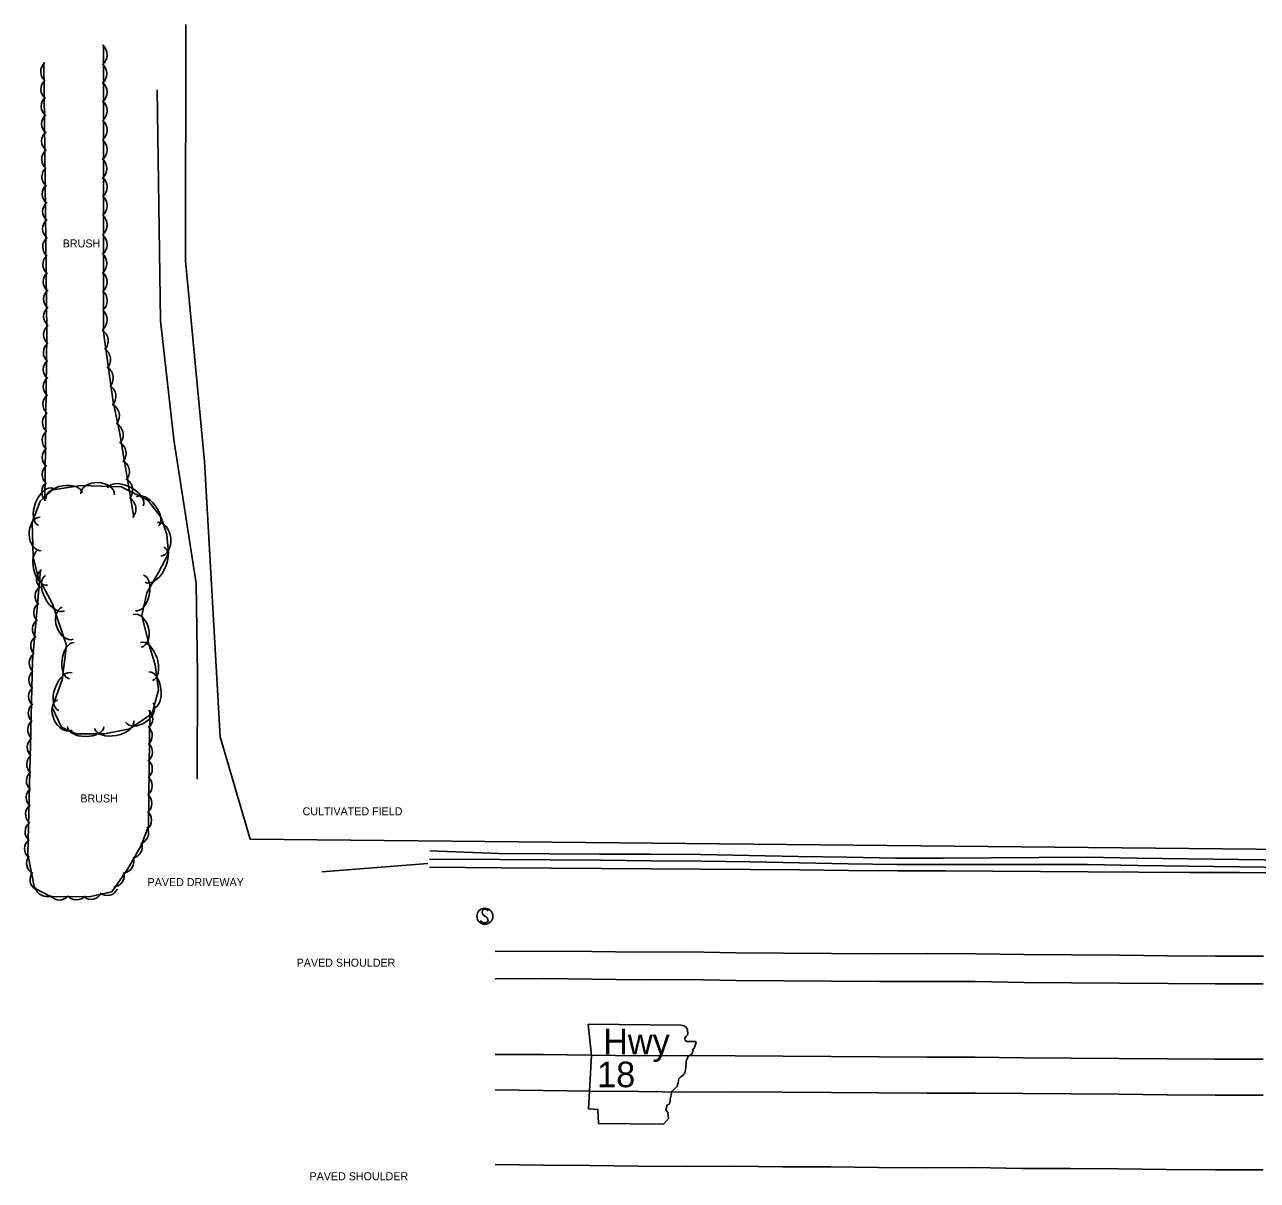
# Model space of a CAD drawing. Extents: x 1802180 to 1804859, y 572524 to 575172.
# Drawn here: x 1802201.2 to 1802586.4, y 573786 to 574147.1 of the extents above; entities that cross this region are included whole.
import ezdxf

# ---------------------------------------------------------------- set-up
doc = ezdxf.new("R2010")
doc.units = 0
for name, color, linetype in [('EX_EDGE_PAVEMENT', 7, 'Continuous'), ('EX_SHOULDER', 7, 'Continuous'), ('S_DITCHLINE', 7, 'Continuous'), ('S_DRIVEWAY_ANNOT', 7, 'Continuous'), ('S_HWY_SYMBOLS', 7, 'Continuous'), ('S_MISC_BOUNDARY', 7, 'Continuous'), ('S_MISC_BOUNDARY_ANNOT', 7, 'Continuous'), ('S_PAVEMENT_CROWN', 7, 'Continuous'), ('S_SHOULDER_ANNOT', 7, 'Continuous'), ('S_SIGN', 7, 'Continuous'), ('S_STREAM', 7, 'Continuous'), ('S_TRAILS', 7, 'Continuous'), ('S_TREE', 7, 'Continuous'), ('S_TREE_ANNOT', 7, 'Continuous')]:
    doc.layers.add(name, color=color, linetype=linetype)

msp = doc.modelspace()

# ---------------------------------------------------------------- linework, layer by layer
at = {"layer": 'EX_EDGE_PAVEMENT'}
for points in [[(1802588.23, 573847.4), (1802573.23, 573847.42), (1802558.48, 573847.5), (1802543.36, 573847.68), (1802528.36, 573847.78), (1802513.47, 573847.87), (1802498.25, 573848.16), (1802483.25, 573848.18), (1802468.33, 573848.18), (1802453.32, 573848.24), (1802438.39, 573848.34), (1802423.46, 573848.49), (1802408.33, 573848.75), (1802393.53, 573848.7), (1802378.53, 573848.9), (1802363.22, 573849.13), (1802348.22, 573849.03)], [(1802588.17, 573789.3), (1802573.17, 573789.32), (1802557.81, 573789.42), (1802542.98, 573789.59), (1802527.98, 573789.69), (1802512.83, 573789.79), (1802498.15, 573790.07), (1802483.15, 573789.99), (1802468.03, 573790.1), (1802453.04, 573790.23), (1802437.95, 573790.31), (1802422.84, 573790.47), (1802408.03, 573790.35), (1802392.76, 573790.46), (1802377.75, 573790.63), (1802363.2, 573790.82), (1802348.2, 573790.98)]]:
    msp.add_lwpolyline(points, dxfattribs=at)
at = {"layer": 'EX_SHOULDER'}
msp.add_lwpolyline([(1802348.18, 573857.56), (1802363.18, 573857.66), (1802378.37, 573857.51), (1802393.35, 573857.31), (1802408.39, 573857.4), (1802423.39, 573857.14), (1802438.32, 573856.99), (1802453.29, 573856.92), (1802468.27, 573856.86), (1802483.23, 573856.87), (1802498.39, 573856.84), (1802513.39, 573856.56), (1802528.29, 573856.46), (1802543.28, 573856.36), (1802558.33, 573856.19), (1802573.28, 573856.1), (1802588.27, 573856.09)], dxfattribs=at)
at = {"layer": 'S_DITCHLINE'}
for points in [[(1802596.5, 573883.74), (1802580.71, 573883.97), (1802564.91, 573884.21), (1802549.11, 573884.44), (1802533.32, 573884.68), (1802518.43, 573884.68), (1802503.55, 573884.68), (1802488.66, 573884.68), (1802473.77, 573884.69), (1802458.52, 573884.96), (1802443.27, 573885.24), (1802428.02, 573885.51), (1802412.77, 573885.79), (1802397.01, 573885.91), (1802381.24, 573886.04), (1802365.47, 573886.17), (1802349.7, 573886.29), (1802327.68, 573886.43)], [(1802596.44, 573886.07), (1802580.57, 573886.3), (1802564.71, 573886.53), (1802548.85, 573886.75), (1802532.99, 573886.98), (1802518.08, 573886.91), (1802503.17, 573886.83), (1802488.26, 573886.75), (1802473.35, 573886.68), (1802458.1, 573886.97), (1802442.86, 573887.26), (1802427.61, 573887.55), (1802412.37, 573887.84), (1802396.61, 573887.91), (1802380.85, 573887.98), (1802365.08, 573888.05), (1802349.32, 573888.12), (1802327.76, 573888.98)], [(1802596.64, 573882.1), (1802580.85, 573882.19), (1802565.05, 573882.27), (1802549.26, 573882.36), (1802533.47, 573882.45), (1802518.61, 573882.53), (1802503.75, 573882.62), (1802488.89, 573882.7), (1802474.03, 573882.78), (1802458.67, 573882.9), (1802443.32, 573883.01), (1802427.96, 573883.13), (1802412.61, 573883.24), (1802397, 573883.36), (1802381.4, 573883.48), (1802365.79, 573883.59), (1802350.19, 573883.71), (1802327.66, 573883.88)]]:
    msp.add_lwpolyline(points, dxfattribs=at)
at = {"layer": 'S_HWY_SYMBOLS'}
msp.add_lwpolyline([(1802377.27, 573834.79), (1802378.27, 573825), (1802377.42, 573808.38), (1802380.3, 573808.21), (1802380.47, 573803.81), (1802400.82, 573803.64), (1802402.34, 573805.33), (1802402.17, 573807.2), (1802401.5, 573808.05), (1802402, 573809.57), (1802402.68, 573809.91), (1802402.85, 573810.76), (1802402.85, 573811.44), (1802403.19, 573812.62), (1802403.36, 573813.81), (1802405.06, 573815.34), (1802405.23, 573815.85), (1802405.4, 573816.52), (1802405.57, 573817.71), (1802406.24, 573818.39), (1802406.92, 573818.9), (1802407.43, 573819.58), (1802407.6, 573820.25), (1802407.77, 573821.1), (1802407.77, 573821.78), (1802407.94, 573822.46), (1802407.94, 573823.48), (1802408.11, 573823.65), (1802408.45, 573824.49), (1802408.62, 573824.83), (1802409.63, 573825.51), (1802409.97, 573826.36), (1802409.97, 573826.87), (1802410.48, 573827.55), (1802410.99, 573829.07), (1802410.82, 573829.41), (1802408.11, 573829.41), (1802407.6, 573829.75), (1802407.43, 573830.6), (1802407.94, 573831.11), (1802408.45, 573831.61), (1802408.28, 573833.14), (1802407.77, 573833.99), (1802407.26, 573834.33), (1802406.24, 573834.5), (1802377.27, 573834.79)], dxfattribs=at)
at = {"layer": 'S_MISC_BOUNDARY'}
msp.add_lwpolyline([(1802879.39, 573886.61), (1802271.63, 573892.66), (1802262.29, 573924.58), (1802257.37, 574010.6), (1802251.41, 574073.29), (1802251.52, 574147.13)], dxfattribs=at)
at = {"layer": 'S_PAVEMENT_CROWN'}
for points in [[(1802588.21, 573823.87), (1802573.21, 573823.89), (1802558.21, 573823.98), (1802543.21, 573824.15), (1802528.21, 573824.25), (1802513.21, 573824.35), (1802498.21, 573824.52), (1802483.21, 573824.54), (1802468.21, 573824.62), (1802453.21, 573824.69), (1802438.21, 573824.81), (1802423.21, 573824.97), (1802408.21, 573825.04), (1802393.21, 573824.92), (1802378.21, 573825.12), (1802363.21, 573825.32), (1802348.21, 573825.33)], [(1802348.21, 573814.3), (1802363.21, 573814.13), (1802378.06, 573813.94), (1802393.06, 573813.78), (1802408.15, 573813.61), (1802423.09, 573813.72), (1802438.13, 573813.56), (1802453.16, 573813.44), (1802468.15, 573813.37), (1802483.19, 573813.25), (1802498.19, 573813.31), (1802513.08, 573813.13), (1802528.13, 573813.03), (1802543.13, 573812.94), (1802558.08, 573812.76), (1802573.19, 573812.67), (1802588.19, 573812.65)]]:
    msp.add_lwpolyline(points, dxfattribs=at)
at = {"layer": 'S_SIGN'}
msp.add_circle((1802344.99, 573868.56), 2.5, dxfattribs=at)
for centre, radius, start, end in [((1802344.83, 573867.74), 1.28, 204.641, 335.359), ((1802345.68, 573869.89), 1.51, 167.1196, 241.9813), ((1802345.06, 573869.83), 0.952, 16.5258, 156.8957), ((1802344.58, 573867.22), 1.4, 358.6529, 73.7063)]:
    msp.add_arc(centre, radius, start, end, dxfattribs=at)
at = {"layer": 'S_STREAM'}
msp.add_lwpolyline([(1802294.01, 573882.47), (1802327.14, 573885.03)], dxfattribs=at)
at = {"layer": 'S_TRAILS'}
msp.add_lwpolyline([(1802242.56, 574126.8), (1802243.66, 574054.55), (1802247.82, 574017.54), (1802254.8, 573972.48), (1802255.19, 573944.13), (1802255.12, 573911.35)], dxfattribs=at)
at = {"layer": 'S_TREE'}
for points in [[(1802225.86, 574140.8), (1802225.87, 574051.01), (1802228.83, 574029.25), (1802230.77, 574019.96), (1802235.29, 573993.25)], [(1802207.46, 573998.36), (1802208.15, 574050.85), (1802207.19, 574135.29)], [(1802218.8, 574003.12), (1802231.39, 574002.73), (1802239.69, 573998.56), (1802243.81, 573993.12), (1802245.63, 573987.8), (1802246.18, 573981.85), (1802243, 573975.93), (1802239.41, 573969.59), (1802237.8, 573962.54), (1802240.07, 573953.22), (1802241.97, 573947.09), (1802243.01, 573939.25), (1802240.99, 573931.92), (1802234.08, 573927.1), (1802226.11, 573925.52), (1802217.25, 573925.56), (1802212.69, 573927.67), (1802209.78, 573933.73), (1802212.86, 573942.42), (1802214.29, 573953.2), (1802209.88, 573966.14), (1802205.39, 573974.55), (1802203.89, 573980.89), (1802203.5, 573991.71), (1802206.06, 573998.24), (1802210.02, 574001.74), (1802218.8, 574003.12)], [(1802240.26, 573932.95), (1802239.92, 573896.69), (1802237.61, 573890.68), (1802233.42, 573883.37), (1802228.41, 573876.18), (1802221.77, 573874.68), (1802209.42, 573874.61), (1802204.23, 573877.33), (1802202.14, 573887.97), (1802203.62, 573948.41), (1802206.15, 573976.82)]]:
    msp.add_lwpolyline(points, dxfattribs=at)
for centre, radius, start, end in [((1802222.94, 574137.7), 4, 309.2056, 50.8025), ((1802209.89, 574132.46), 3.69, 129.8556, 231.4525), ((1802222.86, 574131.84), 4, 309.2056, 50.8025), ((1802209.95, 574126.94), 3.69, 129.8556, 231.4525), ((1802222.94, 574126.04), 4, 309.2056, 50.8025), ((1802210.04, 574121.57), 3.69, 129.8556, 231.4525), ((1802222.98, 574120.21), 4, 309.2056, 50.8025), ((1802210.18, 574116.21), 3.69, 129.8556, 231.4525), ((1802210.17, 574110.8), 3.69, 129.8556, 231.4525), ((1802222.98, 574114.24), 4, 309.2056, 50.8025), ((1802222.94, 574108.04), 4, 309.2056, 50.8025), ((1802210.2, 574105.07), 3.69, 129.8556, 231.4525), ((1802210.26, 574099.56), 3.69, 129.8556, 231.4525), ((1802222.86, 574102.18), 4, 309.2056, 50.8025), ((1802222.94, 574096.37), 4, 309.2056, 50.8025), ((1802210.36, 574094.18), 3.69, 129.8556, 231.4525), ((1802210.49, 574088.82), 3.69, 129.8556, 231.4525), ((1802222.98, 574090.55), 4, 309.2056, 50.8025), ((1802222.98, 574084.57), 4, 309.2056, 50.8025), ((1802210.48, 574083.41), 3.69, 129.8556, 231.4525), ((1802210.51, 574077.69), 3.69, 129.8556, 231.4525), ((1802222.94, 574078.37), 4, 309.2056, 50.8025), ((1802222.86, 574072.51), 4, 309.2056, 50.8025), ((1802210.57, 574072.17), 3.69, 129.8556, 231.4525), ((1802210.67, 574066.79), 3.69, 129.8556, 231.4525), ((1802222.95, 574066.71), 4, 309.2056, 50.8025), ((1802210.8, 574061.44), 3.69, 129.8556, 231.4525), ((1802222.99, 574060.88), 4, 309.2056, 50.8025), ((1802210.79, 574056.03), 3.69, 129.8556, 231.4525), ((1802222.98, 574054.91), 4, 309.2056, 50.8025), ((1802210.81, 574050.23), 3.69, 128.4476, 230.0445), ((1802223.29, 574048.33), 4, 316.9587, 58.5556), ((1802210.73, 574044.72), 3.69, 128.4476, 230.0445), ((1802224, 574042.51), 4, 316.9587, 58.5556), ((1802210.7, 574039.34), 3.69, 128.4476, 230.0445), ((1802210.7, 574033.98), 3.69, 128.4476, 230.0445), ((1802224.86, 574036.78), 4, 316.9587, 58.5556), ((1802225.68, 574031.01), 4, 316.9587, 58.5556), ((1802210.56, 574028.57), 3.69, 128.4476, 230.0445), ((1802210.45, 574022.85), 3.69, 128.4476, 230.0445), ((1802226.79, 574024.93), 4, 321.0046, 62.6015), ((1802227.98, 574018.96), 4, 318.7984, 60.3953), ((1802210.37, 574017.33), 3.69, 128.4476, 230.0445), ((1802210.34, 574011.95), 3.69, 128.4476, 230.0445), ((1802228.88, 574013.17), 4, 318.7984, 60.3953), ((1802229.92, 574007.46), 4, 318.7984, 60.3953), ((1802210.34, 574006.6), 3.69, 128.4476, 230.0445), ((1802210.2, 574001.19), 3.69, 128.4476, 230.0445), ((1802230.93, 574001.72), 4, 318.7984, 60.3953), ((1802231.93, 573995.83), 4, 318.7984, 60.3953), ((1802208.46, 573973.85), 3.56, 124.1179, 225.7148), ((1802207.99, 573968.55), 3.56, 124.1179, 225.7148), ((1802207.56, 573963.39), 3.56, 124.1179, 225.7148), ((1802207.17, 573958.24), 3.56, 124.1179, 225.7148), ((1802206.64, 573953.05), 3.56, 124.1179, 225.7148), ((1802206.17, 573947.72), 3.56, 127.7965, 229.3934), ((1802206.04, 573942.41), 3.56, 127.7965, 229.3934), ((1802205.95, 573937.23), 3.56, 127.7965, 229.3934), ((1802205.89, 573932.07), 3.56, 127.7965, 229.3934), ((1802237.63, 573930.21), 3.56, 308.6755, 50.2725), ((1802205.69, 573926.86), 3.56, 127.7965, 229.3934), ((1802237.51, 573925), 3.56, 308.6755, 50.2725), ((1802205.52, 573921.34), 3.56, 127.7965, 229.3934), ((1802237.54, 573919.84), 3.56, 308.6755, 50.2725), ((1802205.39, 573916.03), 3.56, 127.7965, 229.3934), ((1802237.52, 573914.65), 3.56, 308.6755, 50.2725), ((1802205.3, 573910.85), 3.56, 127.7965, 229.3934), ((1802237.47, 573909.34), 3.56, 308.6755, 50.2725), ((1802205.24, 573905.68), 3.56, 127.7965, 229.3934), ((1802237.39, 573903.82), 3.56, 308.6755, 50.2725), ((1802205.04, 573900.48), 3.56, 127.7965, 229.3934), ((1802237.27, 573898.61), 3.56, 308.6755, 50.2725), ((1802204.88, 573894.96), 3.56, 127.7965, 229.3934), ((1802236.33, 573894.58), 3.56, 288.1666, 29.7635), ((1802204.74, 573889.65), 3.56, 127.7965, 229.3934), ((1802234.39, 573890.21), 3.56, 279.3667, 20.9636), ((1802205.35, 573885.09), 3.56, 140.321, 241.9179), ((1802231.74, 573885.6), 3.56, 279.3667, 20.9636), ((1802206.42, 573880.04), 3.56, 140.321, 241.9179), ((1802228.76, 573881.23), 3.56, 274.3179, 15.9149), ((1802208.07, 573878.25), 3.56, 191.5099, 293.1068), ((1802212.03, 573877.19), 3.56, 219.5408, 321.1377), ((1802217.35, 573877.22), 3.56, 219.5408, 321.1377), ((1802221.96, 573877.39), 3.56, 231.9504, 333.5473), ((1802226.97, 573878.6), 3.56, 231.9504, 333.5473)]:
    msp.add_arc(centre, radius, start, end, dxfattribs=at)
for centre, major_axis, ratio in [((1802207.81, 573996.5), (-2.29, -5.82), 0.55008), ((1802213.52, 574000), (-5.63, -0.89), 0.540699), ((1802224, 574000.42), (-5.28, 0.17), 0.685311), ((1802232.65, 573999.56), (-5.59, 2.81), 0.55008), ((1802239.53, 573995.03), (-3.44, 4.54), 0.540699), ((1802206.18, 573987.98), (0.19, -5.28), 0.685311), ((1802243.22, 573986.33), (-0.48, 5.26), 0.685311), ((1802207.01, 573977.53), (1.31, -5.55), 0.540699), ((1802241.76, 573978.4), (2.96, 5.51), 0.55008), ((1802210.64, 573969.52), (2.95, -5.51), 0.55008), ((1802237.08, 573969.53), (1.27, 5.55), 0.540699), ((1802214.62, 573960.1), (1.7, -5), 0.685311), ((1802236.36, 573957.74), (-1.25, 5.13), 0.685311), ((1802215.93, 573948.39), (-0.75, -5.65), 0.540699), ((1802239.27, 573948.16), (-1.85, 5.97), 0.55008), ((1802213.94, 573938.72), (-2.09, -5.89), 0.55008), ((1802240.73, 573939.23), (-0.75, 5.65), 0.540699), ((1802213.7, 573931.43), (2.29, -4.76), 0.685311), ((1802237, 573932.23), (4.33, 3.02), 0.685311), ((1802229.19, 573928.44), (6.13, 1.22), 0.55008), ((1802220.26, 573927.8), (5.7, -0.02), 0.540699)]:
    msp.add_ellipse(centre, major_axis=major_axis, ratio=ratio, start_param=3.141593, end_param=6.283185, dxfattribs=at)

# ---------------------------------------------------------------- texts
at = {"layer": 'S_DRIVEWAY_ANNOT'}
msp.add_text('PAVED DRIVEWAY', height=2.5, dxfattribs=at).set_placement((1802239.59, 573877.97))
at = {"layer": 'S_HWY_SYMBOLS'}
for s, p in [('Hwy', (1802381.97, 573825.4)), ('18', (1802380.08, 573815.14))]:
    msp.add_text(s, height=8, dxfattribs=at).set_placement(p)
at = {"layer": 'S_MISC_BOUNDARY_ANNOT'}
msp.add_text('CULTIVATED FIELD', height=2.5, dxfattribs=at).set_placement((1802288.02, 573900.1))
at = {"layer": 'S_SHOULDER_ANNOT'}
for p in [(1802286.18, 573852.8), (1802290.2, 573786.08)]:
    msp.add_text('PAVED SHOULDER', height=2.5, dxfattribs=at).set_placement(p)
at = {"layer": 'S_TREE_ANNOT'}
for p in [(1802213.09, 574077.53), (1802218.6, 573904.12)]:
    msp.add_text('BRUSH', height=2.5, dxfattribs=at).set_placement(p)

doc.saveas('drawing.dxf')
